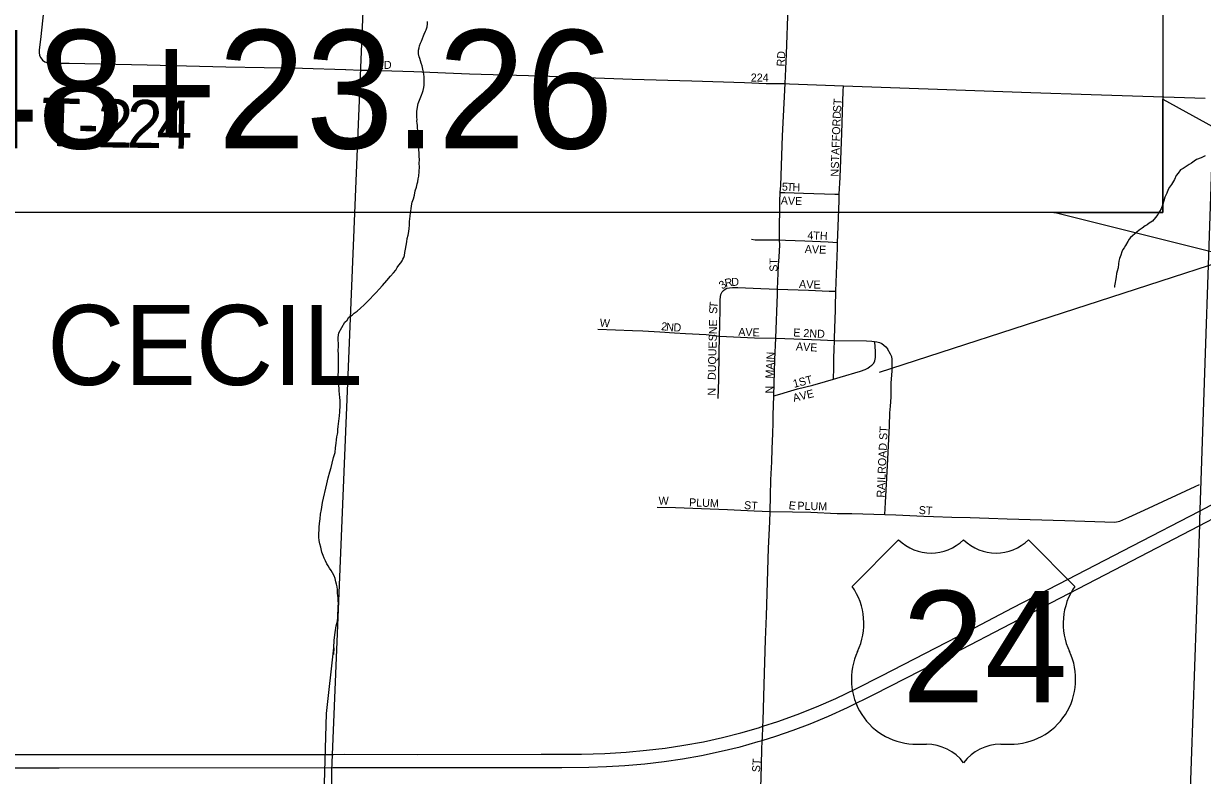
# Model space of a CAD drawing. Extents: x 0 to 64.8, y -5 to 22.
# Drawn here: x 3.279 to 4.674, y 17.005 to 17.895 of the extents above; entities that cross this region are included whole.
import ezdxf

# ---------------------------------------------------------------- set-up
doc = ezdxf.new("R2010")
doc.units = 0
for name, color, linetype in [('GM_X_City_Street', 7, 'Continuous'), ('GM_X_City_Street_Text', 7, 'Continuous'), ('GM_X_Corporation', 7, 'Continuous'), ('GM_X_Corporation_Text', 7, 'Continuous'), ('GM_X_Minor_River', 7, 'Continuous'), ('GM_X_Rail_Line', 7, 'Continuous'), ('GM_X_Township_Road', 7, 'Continuous'), ('GM_X_Township_Road_Text', 7, 'Continuous'), ('GM_X_US_Location', 7, 'Continuous'), ('GM_X_US_Route', 7, 'Continuous'), ('GM_X_US_Shield', 7, 'Continuous'), ('SH_Masking', 7, 'Continuous'), ('SH_Text', 7, 'Continuous')]:
    doc.layers.add(name, color=color, linetype=linetype)

msp = doc.modelspace()

# ---------------------------------------------------------------- linework, layer by layer
at = {"layer": 'GM_X_City_Street'}
for points in [[(4.1799, 17.8237), (4.1813, 17.8587), (4.1836, 17.9145), (4.1854, 17.9641), (4.1875, 18.0262), (4.1898, 18.0913), (4.192, 18.1471), (4.1934, 18.1995), (4.1949, 18.2616), (4.1955, 18.2855), (4.1957, 18.2941)], [(3.6776, 17.8396), (3.6885, 17.8395), (3.7014, 17.8392), (3.7403, 17.8379), (3.8064, 17.8354), (3.8901, 17.8327), (3.9989, 17.8291), (4.0695, 17.8268), (4.1318, 17.8251), (4.1574, 17.8239), (4.1799, 17.8237)], [(4.1741, 17.695), (4.1747, 17.7033), (4.1768, 17.7619), (4.1799, 17.8237)], [(4.1799, 17.8237), (4.1851, 17.8236), (4.2488, 17.8211)], [(4.2438, 17.6927), (4.2448, 17.7126), (4.2468, 17.7652), (4.2486, 17.8147), (4.2488, 17.8211)], [(4.2488, 17.8211), (4.3713, 17.8166), (4.4706, 17.8131), (4.542, 17.8107), (4.677, 17.8063)], [(4.1733, 17.6387), (4.1732, 17.6451), (4.1733, 17.6602), (4.1737, 17.6691), (4.1736, 17.6842), (4.1741, 17.695)], [(4.1741, 17.695), (4.1795, 17.695), (4.2015, 17.694), (4.2385, 17.6928), (4.2438, 17.6927)], [(4.2419, 17.6358), (4.2423, 17.6446), (4.2438, 17.6848), (4.2438, 17.6927)], [(4.1401, 17.6395), (4.1442, 17.6389), (4.1558, 17.6387), (4.1733, 17.6387)], [(4.1709, 17.5804), (4.1721, 17.6087), (4.1726, 17.6188), (4.1734, 17.6327), (4.1733, 17.6387)], [(4.1733, 17.6387), (4.1801, 17.6385), (4.2032, 17.6376), (4.2307, 17.6363), (4.2419, 17.6358)], [(4.24, 17.578), (4.2418, 17.6292), (4.2419, 17.6358)], [(4.1022, 17.5248), (4.1025, 17.538), (4.1029, 17.5576), (4.1031, 17.5682), (4.1039, 17.574), (4.1054, 17.5773)], [(4.1054, 17.5773), (4.1067, 17.5789), (4.1089, 17.5806), (4.111, 17.5817), (4.114, 17.5822), (4.1176, 17.5826), (4.1237, 17.5824), (4.1512, 17.5812), (4.1709, 17.5804)], [(4.1688, 17.5224), (4.1707, 17.5747), (4.1709, 17.5804)], [(4.1709, 17.5804), (4.2074, 17.5793), (4.232, 17.5783), (4.24, 17.578)], [(4.2382, 17.5199), (4.2387, 17.5366), (4.239, 17.5427), (4.2396, 17.5581), (4.2396, 17.5612), (4.2395, 17.5673), (4.2397, 17.5704), (4.24, 17.578)], [(3.9582, 17.5333), (3.9793, 17.5323), (3.9994, 17.5317), (4.0116, 17.5313), (4.0317, 17.5301), (4.0488, 17.5289), (4.0618, 17.5281), (4.0863, 17.5268), (4.1022, 17.5248)], [(4.1005, 17.4512), (4.1013, 17.4737), (4.1019, 17.5047), (4.1022, 17.5248)], [(4.1022, 17.5248), (4.1437, 17.5231), (4.1688, 17.5224)], [(4.1665, 17.4541), (4.1678, 17.4971), (4.1688, 17.5224)], [(4.1688, 17.5224), (4.2217, 17.5206), (4.2382, 17.5199)], [(4.237, 17.4741), (4.2374, 17.4873), (4.2373, 17.4904), (4.2375, 17.4965), (4.2376, 17.4996), (4.2379, 17.5088), (4.2382, 17.5199)], [(4.2382, 17.5199), (4.2762, 17.5192), (4.2823, 17.5189), (4.2856, 17.5185)], [(4.237, 17.4741), (4.2451, 17.4764), (4.2689, 17.4835), (4.2747, 17.4856), (4.2775, 17.487), (4.2801, 17.4888), (4.2825, 17.4907), (4.2846, 17.4931), (4.2861, 17.4958), (4.2869, 17.4997), (4.2869, 17.505), (4.2862, 17.5142), (4.2856, 17.5185)], [(4.2856, 17.5185), (4.2884, 17.5182), (4.2914, 17.5175), (4.2942, 17.5162), (4.2967, 17.5144), (4.2989, 17.5123), (4.3009, 17.5099)], [(4.2979, 17.3139), (4.2986, 17.3279), (4.301, 17.3717), (4.3032, 17.4188), (4.3036, 17.4341), (4.3045, 17.4421), (4.3053, 17.4526), (4.3053, 17.4601), (4.3054, 17.4653), (4.3053, 17.4693), (4.3063, 17.484), (4.3065, 17.4937), (4.3065, 17.4975), (4.3059, 17.5004), (4.3046, 17.5037), (4.3009, 17.5099)], [(4.1665, 17.4541), (4.1737, 17.4563), (4.1826, 17.4591), (4.1945, 17.4624), (4.2126, 17.4671), (4.2275, 17.4712), (4.237, 17.4741)], [(4.1621, 17.3176), (4.1625, 17.3359), (4.1631, 17.3549), (4.164, 17.3764), (4.1645, 17.3916), (4.1651, 17.4096), (4.1656, 17.4224), (4.1658, 17.4316), (4.1665, 17.4541)], [(4.2979, 17.3139), (4.3108, 17.3135), (4.3439, 17.3121), (4.3555, 17.3115), (4.377, 17.3107), (4.3988, 17.3104), (4.4208, 17.3097), (4.4424, 17.3089), (4.5108, 17.3069), (4.5698, 17.305), (4.5757, 17.3059), (4.5867, 17.3107), (4.6047, 17.3189), (4.665, 17.3472), (4.6701, 17.3495)], [(4.0284, 17.3224), (4.0501, 17.322), (4.1118, 17.3198), (4.1433, 17.3182), (4.1621, 17.3176)], [(4.1353, 16.8214), (4.1368, 16.8239), (4.1374, 16.8265), (4.1378, 16.838), (4.1403, 16.8875), (4.1423, 16.9153), (4.1439, 16.9307), (4.1467, 16.9491), (4.1493, 16.9675), (4.1508, 16.983), (4.1513, 17.0017), (4.1524, 17.0355), (4.1528, 17.0466), (4.1529, 17.0492), (4.1535, 17.0633), (4.1538, 17.0698), (4.1551, 17.1129), (4.1567, 17.1656), (4.1577, 17.194), (4.1603, 17.2742), (4.1617, 17.3054), (4.1621, 17.3176)], [(4.1621, 17.3176), (4.1886, 17.3169), (4.2104, 17.3165), (4.2415, 17.3152), (4.2586, 17.315), (4.2979, 17.3139)]]:
    msp.add_lwpolyline(points, dxfattribs=at)
at = {"layer": 'GM_X_Corporation'}
for points in [[(3.6455, 16.8336), (3.6435, 17.0108), (3.6843, 18.0052)], [(4.687, 17.8059), (4.6703, 17.3075), (4.6701, 17.3022), (4.6523, 16.7981)]]:
    msp.add_lwpolyline(points, dxfattribs=at)
at = {"layer": 'GM_X_Minor_River'}
for points in [[(3.6889, 17.5691), (3.6924, 17.5728), (3.696, 17.5765), (3.6995, 17.5803), (3.7034, 17.5847), (3.7084, 17.5907), (3.7127, 17.5959), (3.7163, 17.6), (3.719, 17.603), (3.7209, 17.606), (3.7229, 17.609), (3.7249, 17.6116), (3.7265, 17.6142), (3.7276, 17.6161), (3.7288, 17.618), (3.7296, 17.6202), (3.7297, 17.624), (3.7306, 17.6278), (3.7314, 17.6323), (3.7323, 17.6365), (3.7327, 17.6403), (3.7336, 17.6445), (3.7345, 17.6486), (3.7349, 17.6524), (3.7354, 17.6562), (3.7355, 17.6607), (3.7356, 17.6638), (3.736, 17.6668), (3.7365, 17.6706), (3.7369, 17.6733), (3.7373, 17.6755), (3.7378, 17.6789), (3.7387, 17.6835), (3.7399, 17.6872), (3.7411, 17.6918), (3.742, 17.6967), (3.7436, 17.7012), (3.7445, 17.705), (3.7453, 17.7076), (3.7457, 17.711), (3.7462, 17.7141), (3.7472, 17.7251), (3.7469, 17.7293), (3.747, 17.7338), (3.7467, 17.7376), (3.7468, 17.7414), (3.7465, 17.7456), (3.7466, 17.7494), (3.7463, 17.7532), (3.746, 17.7578), (3.7461, 17.7604), (3.7461, 17.7631), (3.7458, 17.7658), (3.7451, 17.7684), (3.7448, 17.7715), (3.7449, 17.7741), (3.7446, 17.7768), (3.7442, 17.7791), (3.7443, 17.7814), (3.7439, 17.7836), (3.744, 17.7874), (3.7441, 17.7912), (3.7458, 17.8003), (3.7495, 17.8101), (3.7507, 17.8131), (3.7515, 17.8154), (3.7524, 17.8192), (3.7528, 17.8218), (3.7528, 17.8245), (3.7526, 17.8283), (3.7526, 17.8317), (3.7523, 17.8348), (3.752, 17.8374), (3.7513, 17.8409), (3.7503, 17.8447), (3.7492, 17.8477), (3.7485, 17.8508), (3.7474, 17.8535), (3.7467, 17.8554), (3.746, 17.8588), (3.7461, 17.8607), (3.7461, 17.8634), (3.7469, 17.866), (3.747, 17.8683), (3.7482, 17.8717), (3.7494, 17.8739), (3.7518, 17.8804), (3.7526, 17.8822), (3.7542, 17.8856), (3.755, 17.8875), (3.7562, 17.8909), (3.7567, 17.8943), (3.7568, 17.897)], [(4.6767, 17.7384), (4.6721, 17.7358), (4.6667, 17.7337), (4.6637, 17.7318), (4.6606, 17.7296), (4.6579, 17.7278), (4.6544, 17.7256), (4.6509, 17.7234), (4.6478, 17.7216), (4.6447, 17.7178), (4.6427, 17.7148), (4.6404, 17.7103), (4.6368, 17.7043), (4.6345, 17.701), (4.6329, 17.6983), (4.6313, 17.6942), (4.6292, 17.6893), (4.628, 17.6848), (4.6264, 17.6799), (4.6248, 17.6757), (4.6228, 17.6724), (4.6208, 17.669), (4.6181, 17.6652)], [(4.6181, 17.6652), (4.6145, 17.6608), (4.6107, 17.6586), (4.6084, 17.6567), (4.6057, 17.6553), (4.6022, 17.6527), (4.5987, 17.6501), (4.596, 17.6479), (4.5886, 17.6416), (4.5871, 17.6397), (4.5855, 17.6367), (4.5827, 17.6322), (4.5808, 17.6292), (4.5796, 17.6274), (4.5784, 17.6247), (4.5771, 17.6206), (4.5755, 17.6168), (4.5747, 17.6138), (4.5742, 17.6104), (4.5738, 17.6058), (4.5729, 17.6017), (4.5721, 17.599), (4.5716, 17.5949), (4.5708, 17.5907), (4.5703, 17.5884), (4.5695, 17.5846), (4.5694, 17.5827), (4.5691, 17.5828)], [(3.6372, 17.0786), (3.6458, 17.1563), (3.6453, 17.1484), (3.6458, 17.1563), (3.6464, 17.1654), (3.6474, 17.1742), (3.6487, 17.1821), (3.65, 17.1878), (3.6504, 17.1923), (3.6505, 17.1969), (3.651, 17.2007), (3.6511, 17.2056), (3.6512, 17.2086), (3.6509, 17.2121), (3.651, 17.2151), (3.6506, 17.2181), (3.6503, 17.2204), (3.65, 17.2227), (3.65, 17.225), (3.6497, 17.2284), (3.649, 17.2315), (3.6483, 17.2342), (3.6473, 17.238), (3.6462, 17.2414), (3.6444, 17.2449), (3.6426, 17.2476), (3.6407, 17.2503), (3.6393, 17.253), (3.6374, 17.2557), (3.636, 17.2591), (3.6345, 17.2622), (3.6331, 17.2653), (3.6316, 17.2695), (3.6306, 17.2752), (3.6292, 17.279), (3.6285, 17.2832), (3.6282, 17.287), (3.6279, 17.2897), (3.628, 17.2924), (3.6284, 17.295), (3.6285, 17.2988), (3.629, 17.3034), (3.6295, 17.3087), (3.63, 17.3143), (3.6313, 17.32), (3.6326, 17.328), (3.6376, 17.3503), (3.6393, 17.3571), (3.641, 17.3643), (3.6426, 17.3695), (3.6439, 17.3748), (3.6456, 17.3812), (3.6472, 17.3873), (3.6477, 17.3926), (3.6486, 17.3983), (3.6491, 17.4021), (3.6495, 17.4059), (3.65, 17.4089), (3.6504, 17.4111), (3.6505, 17.4146), (3.6509, 17.418), (3.6514, 17.421), (3.6519, 17.4244), (3.6523, 17.4274), (3.6524, 17.4305), (3.6529, 17.4354), (3.6534, 17.443), (3.6535, 17.446), (3.6532, 17.4487), (3.6529, 17.4525), (3.6526, 17.4563), (3.6523, 17.4601), (3.652, 17.4639), (3.6513, 17.4681), (3.651, 17.4715), (3.6511, 17.4738), (3.6511, 17.4776), (3.6513, 17.4841), (3.6514, 17.4886), (3.6515, 17.492), (3.6515, 17.4943), (3.6512, 17.497), (3.6513, 17.5), (3.6513, 17.5034), (3.6511, 17.508), (3.6512, 17.5126), (3.6513, 17.5164), (3.651, 17.5202), (3.651, 17.5232), (3.6515, 17.5259), (3.6519, 17.5289), (3.6587, 17.5413), (3.6614, 17.5439), (3.6637, 17.5472), (3.6676, 17.5498), (3.6699, 17.552), (3.6734, 17.5546), (3.6773, 17.558), (3.6816, 17.562), (3.6854, 17.5654), (3.6889, 17.5691)], [(3.5518, 14.1), (3.6372, 17.0786)]]:
    msp.add_lwpolyline(points, dxfattribs=at)
at = {"layer": 'GM_X_Rail_Line'}
msp.add_lwpolyline([(4.2913, 17.4823), (4.783, 17.6416), (5.7936, 17.9743), (6.8537, 18.3208), (7.9347, 18.672), (8.7178, 18.9261), (8.9, 18.9851)], dxfattribs=at)
at = {"layer": 'GM_X_Township_Road'}
for points in [[(3.3024, 17.9084), (3.3016, 17.9016), (3.2986, 17.876), (3.2973, 17.8636), (3.2972, 17.8603), (3.2977, 17.857), (3.299, 17.854), (3.3012, 17.8514), (3.304, 17.8496), (3.3071, 17.8484), (3.3159, 17.8478), (3.3325, 17.8478), (3.4249, 17.8459), (3.5182, 17.8437), (3.6086, 17.8421), (3.6596, 17.8403)], [(3.6596, 17.8403), (3.66, 17.8403), (3.6776, 17.8396)]]:
    msp.add_lwpolyline(points, dxfattribs=at)
at = {"layer": 'GM_X_US_Route'}
for points in [[(4.6697, 17.3005), (4.7209, 17.3272), (4.9103, 17.4252), (4.9975, 17.4703), (5.0572, 17.501), (5.0911, 17.518), (5.1143, 17.5286), (5.1331, 17.5366), (5.1522, 17.544), (5.1745, 17.5518), (5.1751, 17.552)], [(3.1258, 17.0298), (3.2874, 17.0298), (3.6453, 17.0301), (3.658, 17.0302), (3.7444, 17.0301), (3.8911, 17.0303), (3.939, 17.0305), (3.9663, 17.0313), (3.9917, 17.0327), (4.0158, 17.0349), (4.038, 17.0375), (4.0601, 17.0409), (4.0833, 17.0451), (4.1057, 17.05), (4.1274, 17.0555), (4.1482, 17.0616), (4.1535, 17.0633), (4.1712, 17.0691), (4.194, 17.0774), (4.2171, 17.0865), (4.2399, 17.0964), (4.2634, 17.1076), (4.294, 17.1229), (4.3972, 17.1764), (4.449, 17.2034), (4.5031, 17.2314), (4.5908, 17.2769), (4.6701, 17.318), (4.7045, 17.3359)], [(3.6447, 17.0146), (3.6677, 17.0146), (3.8125, 17.0147), (3.9157, 17.0147), (3.9474, 17.015), (3.9686, 17.0156), (3.9903, 17.0169), (4.0139, 17.0189), (4.0368, 17.0216), (4.0583, 17.0247), (4.081, 17.0288), (4.1041, 17.0337), (4.1265, 17.0392), (4.1481, 17.0452), (4.1528, 17.0466), (4.1689, 17.0516), (4.1895, 17.0587), (4.2093, 17.0662), (4.2311, 17.0754), (4.2537, 17.0857), (4.2855, 17.1014), (4.3403, 17.1295), (4.4373, 17.18), (4.4837, 17.204), (4.5803, 17.254), (4.6697, 17.3005)], [(2.1, 16.7212), (2.4096, 16.822), (2.5235, 16.8592), (2.5975, 16.8835), (2.6372, 16.8963), (2.6584, 16.9032), (2.7218, 16.9236), (2.8783, 16.9748), (2.908, 16.9839), (2.9308, 16.9903), (2.95, 16.995), (2.9701, 16.9994), (2.9908, 17.0032), (3.0148, 17.0069), (3.0369, 17.0097), (3.0586, 17.0117), (3.0796, 17.013), (3.1063, 17.0139), (3.148, 17.0142), (3.3208, 17.0143), (3.6447, 17.0146)]]:
    msp.add_lwpolyline(points, dxfattribs=at)
at = {"layer": 'GM_X_US_Shield'}
for p, q in [((4.314, 17.2838), (4.2591, 17.2289)), ((4.5227, 17.2289), (4.4678, 17.2838)), ((4.336, 17.0421), (4.347, 17.0421)), ((4.4349, 17.0421), (4.4458, 17.0421))]:
    msp.add_line(p, q, dxfattribs=at)
for centre, radius, start, end in [((4.3525, 17.3231), 0.0549, 225.573, 314.427), ((4.4294, 17.3231), 0.0549, 225.573, 314.427), ((4.1961, 17.1848), 0.0769, 334.5471, 35.0009), ((4.5857, 17.1848), 0.0769, 144.9991, 205.4529), ((4.3351, 17.119), 0.0769, 154.8319, 270.6383), ((4.4467, 17.119), 0.0769, 269.3617, 25.1681), ((4.347, 16.9872), 0.0549, 36.8699, 90), ((4.4349, 16.9872), 0.0549, 90, 143.1301)]:
    msp.add_arc(centre, radius, start, end, dxfattribs=at)
at = {"layer": 'SH_Masking'}
msp.add_lwpolyline([(2.5541, 18.1613), (4.6267, 18.1613), (4.6267, 17.6713), (2.5541, 17.6713)], close=True, dxfattribs=at)
at = {"layer": 'SH_Text'}
for p, q in [((4.6267, 17.6713), (4.6267, 17.8051)), ((4.4976, 17.6713), (4.6267, 17.6713))]:
    msp.add_line(p, q, dxfattribs=at)
msp.add_lwpolyline([(2.5541, 18.1613), (4.6267, 18.1613), (4.6267, 17.6713), (2.5541, 17.6713)], close=True, dxfattribs=at)
msp.add_lwpolyline([(4.6267, 17.8051), (5.1804, 17.5006), (4.4976, 17.6713)], dxfattribs=at)

# ---------------------------------------------------------------- texts
at = {"layer": 'GM_X_City_Street_Text'}
for s, rotation, p in [('RD', 86.9861, (4.1792, 17.8437)), ('RD', 0, (3.6959, 17.8411)), ('224', 0, (4.1392, 17.8261)), ('ST', 86.4228, (4.2458, 17.7896)), ('STAFFORD', 87.8786, (4.2433, 17.7229)), ('N', 90, (4.2433, 17.7136)), ('5', 358.7197, (4.1759, 17.6971)), ('T', 357.595, (4.1816, 17.6969)), ('H', 357.3982, (4.1883, 17.6967)), ('AVE', 358.0262, (4.1746, 17.6808)), ('4TH', 357.7107, (4.206, 17.6396)), ('AVE', 358.0261, (4.2029, 17.6233)), ('ST', 90, (4.1708, 17.6011)), ('3', 35.2881, (4.1055, 17.5799)), ('R', 11.4659, (4.1093, 17.5829)), ('D', 1.5957, (4.1162, 17.5843)), ('A', 356.0409, (4.196, 17.5821)), ('V', 358.4868, (4.2048, 17.5815)), ('E', 359.914, (4.2134, 17.5812)), ('T', 84.3152, (4.0995, 17.5575)), ('S', 88.8048, (4.0994, 17.5511)), ('W', 355.6039, (3.9602, 17.5362)), ('2', 354.0882, (4.0328, 17.5321)), ('N', 354.5575, (4.0387, 17.5314)), ('D', 358.5689, (4.0477, 17.5306)), ('DUQUESNE', 88.6516, (4.0977, 17.4729)), ('A', 357.617, (4.1243, 17.5254)), ('V', 357.6087, (4.1326, 17.5251)), ('E', 358.8863, (4.1412, 17.5247)), ('E 2ND', 357.0659, (4.1893, 17.5246)), ('AVE', 356.0569, (4.1924, 17.5083)), ('MAIN', 86.9061, (4.1658, 17.4745)), ('1ST', 14.6249, (4.1905, 17.4637)), ('N', 90, (4.1658, 17.457)), ('N', 90, (4.0977, 17.4545)), ('AVE', 13.5702, (4.1901, 17.447)), ('RAILROAD ST', 87.4833, (4.2975, 17.3337)), ('W', 0, (4.0301, 17.3254)), ('PLUM', 357.6596, (4.066, 17.3237)), ('ST', 356.1881, (4.131, 17.3204)), ('E', 352.8783, (4.1836, 17.3204)), ('PLUM', 358.532, (4.1943, 17.3196)), ('ST', 356.4256, (4.3377, 17.3146)), ('ST', 86.4254, (4.15, 17.0087))]:
    msp.add_text(s, height=0.00947, rotation=rotation, dxfattribs=at).set_placement(p)
at = {"layer": 'GM_X_Corporation_Text'}
msp.add_text('CECIL', height=0.0947, rotation=0, dxfattribs=at).set_placement((3.3067, 17.4671))
at = {"layer": 'GM_X_Township_Road_Text'}
for s, rotation, p in [('T', 358.0368, (3.2987, 17.7504)), ('2', 359.0558, (3.3656, 17.7484)), ('2', 359.1031, (3.4006, 17.7479)), ('4', 359.108, (3.4356, 17.7473)), ('-', 358.9229, (3.3421, 17.7489))]:
    msp.add_text(s, height=0.0568, rotation=rotation, dxfattribs=at).set_placement(p)
at = {"layer": 'GM_X_US_Location'}
for s in ['/', '0']:
    msp.add_text(s, height=0.000189, dxfattribs=at).set_placement((4.3908, 17.1564))
msp.add_text('24', height=0.000189, rotation=0, dxfattribs=at).set_placement((4.3517, 17.1172))
at = {"layer": 'GM_X_US_Shield'}
msp.add_text('24', height=0.13184, dxfattribs=at).set_placement((4.3179, 17.0916))
at = {"layer": 'SH_Text'}
msp.add_text('STA. 848+23.26', height=0.14, dxfattribs=at).set_placement((2.6185, 17.747))

doc.saveas('drawing.dxf')
